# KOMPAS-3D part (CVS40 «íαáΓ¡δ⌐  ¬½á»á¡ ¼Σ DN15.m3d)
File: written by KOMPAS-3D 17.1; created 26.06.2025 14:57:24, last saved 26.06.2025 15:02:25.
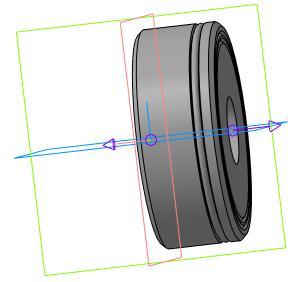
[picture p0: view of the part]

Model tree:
1. Эскиз:1
2. Элемент вращения:1
     Угол 1 = 360
3. Присоединительная точка:1
4. Присоединительная точка:2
